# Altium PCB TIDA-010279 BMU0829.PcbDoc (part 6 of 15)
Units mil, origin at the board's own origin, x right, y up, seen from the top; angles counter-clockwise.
Board outline 11269.69 x 4438.98 mil, 4 copper layers (Top Layer, Signal Layer 1, Signal Layer 2, Bottom Layer), stack 61.6 mil thick; 1494 components, 725 nets, 3766 pads, 2728 vias.
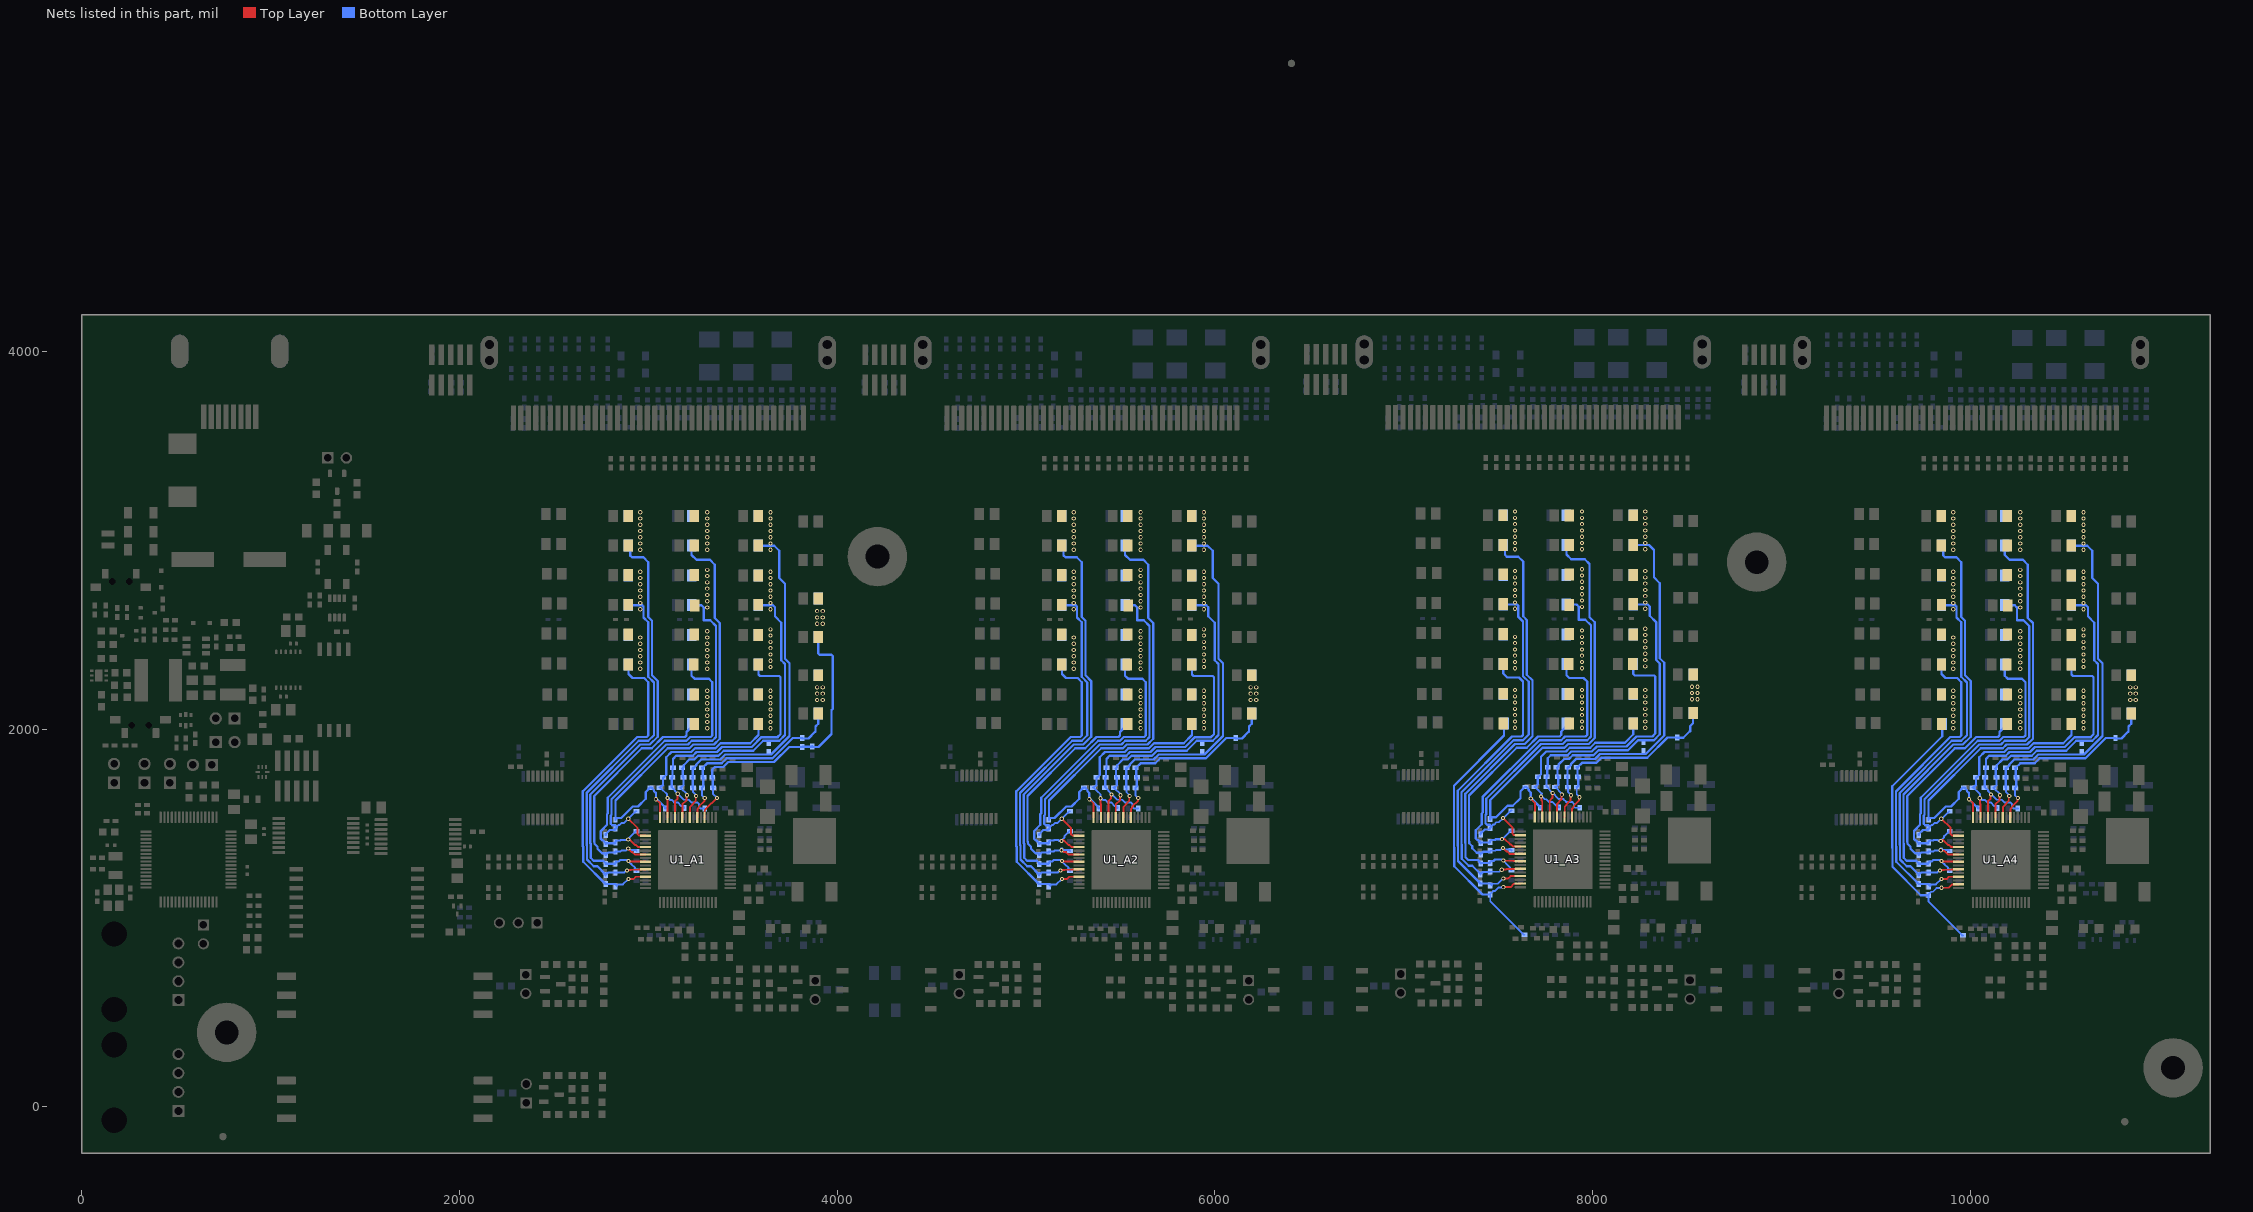
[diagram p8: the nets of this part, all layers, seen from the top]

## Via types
v1: diameter 22.01, hole 12.01, Top Layer to Bottom Layer, tented both sides, 2578 vias
v2: diameter 19.68, hole 7.87, Top Layer to Bottom Layer, tented both sides, 144 vias
v3: diameter 92.52, hole 49.21, Top Layer to Bottom Layer, 4 vias
v4: diameter 19.68, hole 7.87, Top Layer to Bottom Layer, 2 vias

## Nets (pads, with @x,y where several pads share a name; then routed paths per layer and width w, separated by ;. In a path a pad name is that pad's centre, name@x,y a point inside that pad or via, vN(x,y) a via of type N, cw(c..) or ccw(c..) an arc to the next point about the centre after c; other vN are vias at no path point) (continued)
CB4_A3: C15_A3.2 C34_A3.1 R27_A3.2 R30_A3.2 R33_A3.2 R38_A3.2 U1_A3.31 | length 1589.5
  Top Layer w10: v1@7525.45,1163.14 7564.79,1163.14 7582.95,1181.31 7615.77,1181.31 U1_A3.31@7616.67,1182.21
  Bottom Layer w10: C15_A3.2@7455.76,1125.64 7472.42,1142.3 7481.35,1142.3 7499.9,1160.85 7523.15,1160.85 v1@7525.45,1163.14 ; C15_A3.2@7457.73,1123.67 7457.73,1088.81 7635.64,910.9 C34_A3.1@7639.58,910.9
  Bottom Layer w12: C15_A3.2@7453.4,1123.67 7417.01,1123.67 7266.78,1273.91 7266.78,1371.84 7265.1,1373.52 7265.1,1700.42 7530.51,1965.84 R38_A3.2@7530.51,2029.14
  other v1: 7526.85,1163.14 7588.88,2007.46 7588.88,2040.64 7588.88,2073.83 7588.88,2107.01 7588.88,2140.2 7588.88,2173.38 7588.88,2206.57
CB4_A4: C15_A4.2 C34_A4.1 R27_A4.2 R30_A4.2 R33_A4.2 R38_A4.2 U1_A4.31 | length 1589.5
  Top Layer w10: v1@9845.68,1159.94 9885.02,1159.94 9903.18,1178.1 9936,1178.1 U1_A4.31@9936.9,1179
  Bottom Layer w10: C15_A4.2@9775.99,1122.43 9792.65,1139.09 9801.58,1139.09 9820.13,1157.64 9843.38,1157.64 v1@9845.68,1159.94 ; C15_A4.2@9777.96,1120.47 9777.96,1085.6 9955.87,907.69 C34_A4.1@9959.81,907.69
  Bottom Layer w12: C15_A4.2@9773.63,1120.47 9737.24,1120.47 9587.01,1270.7 9587.01,1368.63 9585.33,1370.32 9585.33,1697.21 9850.74,1962.63 R38_A4.2@9850.74,2025.93
  other v1: 9847.08,1159.94 9909.11,2004.25 9909.11,2037.44 9909.11,2070.62 9909.11,2103.81 9909.11,2136.99 9909.11,2170.17 9909.11,2203.36
CB5_A1: C2_A1.2 C15_A1.1 R13_A1.2 R16_A1.2 R20_A1.2 R23_A1.2 U1_A1.29 | length 1700.8
  Top Layer w10: v1@2893.84,1206.14 2921.43,1206.14 2933.66,1218.37 U1_A1.29@2985.06,1218.37
  Bottom Layer w10: C15_A1.1@2830.51,1175.39 2832.93,1177.81 2865.5,1177.81 v1@2893.84,1206.14
  Bottom Layer w12: C2_A1.2@2773.73,1179.32 2826.59,1179.32 2830.51,1175.39 2832.16,1173.75 C15_A1.1@2834.65,1171.26 ; C2_A1.2@2773.76,1179.35 2655.04,1298.07 2655.04,1376.87 2653.36,1378.55 2653.36,1670.23 2940.87,1957.75 2991.43,1957.75 2999.56,1965.88 2999.56,2248.51 2978.05,2270.02 2916.27,2270.02 2894.76,2291.52 R20_A1.2@2894.76,2341.02
  other v1: 2895.24,1206.14 2957.26,2319.21 2957.26,2352.4 2957.26,2385.58 2957.26,2418.77 2957.26,2451.95 2957.26,2485.14
CB5_A2: C2_A2.2 C15_A2.1 R13_A2.2 R16_A2.2 R20_A2.2 R23_A2.2 U1_A2.29 | length 1700.8
  Top Layer w10: v1@5188.85,1206.14 5216.44,1206.14 5228.67,1218.37 U1_A2.29@5280.07,1218.37
  Bottom Layer w10: C15_A2.1@5125.53,1175.39 5127.95,1177.81 5160.52,1177.81 v1@5188.85,1206.14
  Bottom Layer w12: C2_A2.2@5068.74,1179.32 5121.6,1179.32 5125.53,1175.39 5127.17,1173.75 C15_A2.1@5129.66,1171.26 ; C2_A2.2@5068.77,1179.35 4950.06,1298.07 4950.06,1376.87 4948.37,1378.55 4948.37,1670.23 5235.89,1957.75 5286.45,1957.75 5294.57,1965.88 5294.57,2248.51 5273.07,2270.02 5211.28,2270.02 5189.78,2291.52 R20_A2.2@5189.78,2341.02
  other v1: 5190.25,1206.14 5252.28,2319.21 5252.28,2352.4 5252.28,2385.58 5252.28,2418.77 5252.28,2451.95 5252.28,2485.14
CB5_A3: C2_A3.2 C15_A3.1 R13_A3.2 R16_A3.2 R20_A3.2 R23_A3.2 U1_A3.29 | length 1700.8
  Top Layer w10: v1@7525.45,1209.35 7553.04,1209.35 7565.27,1221.58 U1_A3.29@7616.67,1221.58
  Bottom Layer w10: C15_A3.1@7462.13,1178.6 7464.54,1181.02 7497.12,1181.02 v1@7525.45,1209.35
  Bottom Layer w12: C15_A3.1@7466.26,1174.47 7463.77,1176.96 7462.13,1178.6 7458.2,1182.53 C2_A3.2@7405.34,1182.53 7286.65,1301.28 7286.65,1380.07 7284.97,1381.76 7284.97,1673.44 7572.49,1960.96 7623.04,1960.96 7631.17,1969.08 7631.17,2251.72 7609.66,2273.22 7547.88,2273.22 7526.37,2294.73 R20_A3.2@7526.37,2344.23
  other v1: 7526.85,1209.35 7588.88,2322.42 7588.88,2355.6 7588.88,2388.79 7588.88,2421.97 7588.88,2455.16 7588.88,2488.34
CB5_A4: C2_A4.2 C15_A4.1 R13_A4.2 R16_A4.2 R20_A4.2 R23_A4.2 U1_A4.29 | length 1700.8
  Top Layer w10: v1@9845.68,1206.14 9873.27,1206.14 9885.5,1218.37 U1_A4.29@9936.9,1218.37
  Bottom Layer w10: C15_A4.1@9782.36,1175.39 9784.77,1177.81 9817.34,1177.81 v1@9845.68,1206.14
  Bottom Layer w12: C2_A4.2@9725.57,1179.32 9778.43,1179.32 9782.36,1175.39 9784,1173.75 C15_A4.1@9786.49,1171.26 ; C2_A4.2@9725.6,1179.35 9606.88,1298.07 9606.88,1376.87 9605.2,1378.55 9605.2,1670.23 9892.72,1957.75 9943.27,1957.75 9951.4,1965.88 9951.4,2248.51 9929.89,2270.02 9868.11,2270.02 9846.6,2291.52 R20_A4.2@9846.6,2341.02
  other v1: 9847.08,1206.14 9909.11,2319.21 9909.11,2352.4 9909.11,2385.58 9909.11,2418.77 9909.11,2451.95 9909.11,2485.14
CB6_A1: C2_A1.1 C94_A1.2 R1_A1.2 R4_A1.2 R7_A1.2 R10_A1.2 U1_A1.27 | length 1978.8
  Top Layer w10: v1(2886.57,1251.9) 2888.86,1254.2 2909.5,1254.2 2910.64,1255.34 2949.84,1255.34 2951.34,1256.84 2984.15,1256.84 U1_A1.27@2985.06,1257.74
  Bottom Layer w10: C94_A1.2@2826.12,1241.66 2873.08,1241.66 2883.32,1251.9 v1(2886.57,1251.9)
  Bottom Layer w12: C2_A1.1@2773.73,1226.56 C2_A1.1@2773.73,1230.5 ; C94_A1.2@2824.8,1240.16 2787.32,1240.16 2783.47,1236.31 2779.54,1236.31 C2_A1.1@2773.73,1230.5 ; R7_A1.2@2894.76,2656.12 2967.73,2656.12 2974.76,2649.09 2974.76,2590.68 2999.56,2565.88 2999.56,2276.61 3029.38,2246.79 3029.38,1967.59 2999.66,1937.87 2949.11,1937.87 2673.23,1662 2673.23,1386.78 2674.91,1385.1 2674.91,1310.04 2711.36,1273.59 2730.63,1273.59 C2_A1.1@2773.73,1230.5
  other v1: 2957.26,2634.17 2957.26,2667.36 2957.26,2700.54 2957.26,2733.73 2957.26,2766.91 2957.26,2800.1 2957.26,2833.28
CB6_A2: C2_A2.1 C94_A2.2 R1_A2.2 R4_A2.2 R7_A2.2 R10_A2.2 U1_A2.27 | length 1978.8
  Top Layer w10: v1(5181.58,1251.9) 5183.88,1254.2 5204.52,1254.2 5205.66,1255.34 5244.86,1255.34 5246.36,1256.84 5279.17,1256.84 U1_A2.27@5280.07,1257.74
  Bottom Layer w10: C94_A2.2@5121.14,1241.66 5168.1,1241.66 5178.33,1251.9 v1(5181.58,1251.9)
  Bottom Layer w12: C2_A2.1@5068.74,1226.56 C2_A2.1@5068.74,1230.5 ; C94_A2.2@5119.82,1240.16 5082.34,1240.16 5078.49,1236.31 5074.55,1236.31 C2_A2.1@5068.74,1230.5 ; R7_A2.2@5189.78,2656.12 5262.74,2656.12 5269.77,2649.09 5269.77,2590.68 5294.57,2565.88 5294.57,2276.61 5324.4,2246.79 5324.4,1967.59 5294.68,1937.87 5244.12,1937.87 4968.25,1662 4968.25,1386.78 4969.93,1385.1 4969.93,1310.04 5006.38,1273.59 5025.65,1273.59 C2_A2.1@5068.74,1230.5
  other v1: 5252.28,2634.17 5252.28,2667.36 5252.28,2700.54 5252.28,2733.73 5252.28,2766.91 5252.28,2800.1 5252.28,2833.28
CB6_A3: C2_A3.1 C94_A3.2 R1_A3.2 R4_A3.2 R7_A3.2 R10_A3.2 U1_A3.27 | length 1978.8
  Top Layer w10: v1(7518.18,1255.11) 7520.48,1257.41 7541.12,1257.41 7542.26,1258.55 7581.45,1258.55 7582.95,1260.05 7615.77,1260.05 U1_A3.27@7616.67,1260.95
  Bottom Layer w10: C94_A3.2@7457.73,1244.87 7504.69,1244.87 7514.93,1255.11 v1(7518.18,1255.11)
  Bottom Layer w12: C2_A3.1@7405.34,1229.77 C2_A3.1@7405.34,1233.71 ; C94_A3.2@7456.42,1243.37 7418.93,1243.37 7415.09,1239.52 7411.15,1239.52 C2_A3.1@7405.34,1233.71 ; R7_A3.2@7526.37,2659.32 7599.34,2659.32 7606.37,2652.29 7606.37,2593.89 7631.17,2569.09 7631.17,2279.82 7661,2250 7661,1970.8 7631.27,1941.08 7580.72,1941.08 7304.84,1665.21 7304.84,1389.99 7306.53,1388.31 7306.53,1313.25 7342.97,1276.8 7362.25,1276.8 C2_A3.1@7405.34,1233.71
  other v1: 7588.88,2637.38 7588.88,2670.57 7588.88,2703.75 7588.88,2736.93 7588.88,2770.12 7588.88,2803.3 7588.88,2836.49
CB6_A4: C2_A4.1 C94_A4.2 R1_A4.2 R4_A4.2 R7_A4.2 R10_A4.2 U1_A4.27 | length 1978.8
  Top Layer w10: v1(9838.41,1251.9) 9840.71,1254.2 9861.35,1254.2 9862.49,1255.34 9901.68,1255.34 9903.18,1256.84 9936,1256.84 U1_A4.27@9936.9,1257.74
  Bottom Layer w10: C94_A4.2@9777.96,1241.66 9824.92,1241.66 9835.16,1251.9 v1(9838.41,1251.9)
  Bottom Layer w12: C2_A4.1@9725.57,1226.56 C2_A4.1@9725.57,1230.5 ; C94_A4.2@9776.65,1240.16 9739.16,1240.16 9735.32,1236.31 9731.38,1236.31 C2_A4.1@9725.57,1230.5 ; R7_A4.2@9846.6,2656.12 9919.57,2656.12 9926.6,2649.09 9926.6,2590.68 9951.4,2565.88 9951.4,2276.62 9981.23,2246.79 9981.23,1967.59 9951.5,1937.87 9900.95,1937.87 9625.07,1662 9625.07,1386.78 9626.76,1385.1 9626.76,1310.04 9663.2,1273.59 9682.48,1273.59 C2_A4.1@9725.57,1230.5
  other v1: 9909.11,2634.17 9909.11,2667.36 9909.11,2700.54 9909.11,2733.73 9909.11,2766.91 9909.11,2800.1 9909.11,2833.28
CB7_A1: C73_A1.2 C94_A1.1 C97_A1.2 R70_A1.2 R73_A1.2 R77_A1.2 R81_A1.2 U1_A1.25 | length 2316.9
  Top Layer w10: v1@2895.24,1299.92 2949.43,1299.92 2951.34,1298.02 2984.15,1298.02 U1_A1.25@2985.06,1297.11
  Bottom Layer w10: v1@2893.96,1301.09 2909.85,1285.21 2909.85,1284.83 2929.76,1264.93 2929.76,1256.19 2936.57,1249.38 C97_A1.2@2938.47,1249.38
  Bottom Layer w12: C94_A1.1@2824.8,1289.37 2822.69,1287.25 2776.07,1287.25 C73_A1.2@2774.41,1285.6 2774.41,1289.54 2760.85,1303.1 2709.96,1303.1 2694.79,1318.27 2694.79,1393.33 2693.11,1395.01 2693.11,1653.77 2957.34,1918 3007.89,1918 3049.26,1959.36 3049.26,2255.02 3019.43,2284.85 3019.43,2574.11 2999.93,2593.61 2999.93,2883.66 2973.84,2909.75 2913.49,2909.75 2903.54,2919.7 2903.54,2962.42 R77_A1.2@2894.76,2971.21 ; C94_A1.1@2826.12,1292.84 2831.93,1298.65 2843.5,1298.65 2851.41,1306.56 2887.06,1306.56 2892.53,1301.09 2893.96,1301.09 v1(2895.24,1301.09)
  other v1: 2957.26,2949.13 2957.26,2982.32 2957.26,3015.5 2957.26,3048.69 2957.26,3081.87 2957.26,3115.06 2957.26,3148.24
CB7_A2: C73_A2.2 C94_A2.1 C97_A2.2 R70_A2.2 R73_A2.2 R77_A2.2 R81_A2.2 U1_A2.25 | length 2316.9
  Top Layer w10: v1@5190.25,1299.92 5244.45,1299.92 5246.36,1298.02 5279.17,1298.02 U1_A2.25@5280.07,1297.11
  Bottom Layer w10: v1@5188.98,1301.09 5204.87,1285.21 5204.87,1284.83 5224.77,1264.93 5224.77,1256.19 5231.58,1249.38 C97_A2.2@5233.49,1249.38
  Bottom Layer w12: C94_A2.1@5119.82,1289.37 5117.7,1287.25 5071.08,1287.25 C73_A2.2@5069.43,1285.6 5069.43,1289.54 5055.87,1303.1 5004.98,1303.1 4989.8,1318.27 4989.8,1393.33 4988.12,1395.01 4988.12,1653.77 5252.35,1918 5302.91,1918 5344.27,1959.36 5344.27,2255.02 5314.45,2284.85 5314.45,2574.11 5294.94,2593.61 5294.94,2883.66 5268.86,2909.75 5208.51,2909.75 5198.56,2919.7 5198.56,2962.42 R77_A2.2@5189.78,2971.21 ; C94_A2.1@5121.14,1292.84 5126.95,1298.65 5138.52,1298.65 5146.43,1306.56 5182.08,1306.56 5187.55,1301.09 5188.98,1301.09 v1(5190.25,1301.09)
  other v1: 5252.28,2949.13 5252.28,2982.32 5252.28,3015.5 5252.28,3048.69 5252.28,3081.87 5252.28,3115.06 5252.28,3148.24
CB7_A3: C73_A3.2 C94_A3.1 C97_A3.2 R70_A3.2 R73_A3.2 R77_A3.2 R81_A3.2 U1_A3.25 | length 2316.9
  Top Layer w10: v1@7526.85,1303.13 7581.05,1303.13 7582.95,1301.23 7615.77,1301.23 U1_A3.25@7616.67,1300.32
  Bottom Layer w10: v1@7525.58,1304.3 7541.47,1288.41 7541.47,1288.04 7561.37,1268.14 7561.37,1259.4 7568.18,1252.59 C97_A3.2@7570.09,1252.59
  Bottom Layer w12: C94_A3.1@7456.42,1292.58 7454.3,1290.46 7407.68,1290.46 C73_A3.2@7406.02,1288.81 7406.02,1292.75 7392.46,1306.31 7341.57,1306.31 7326.4,1321.48 7326.4,1396.54 7324.72,1398.22 7324.72,1656.97 7588.95,1921.21 7639.51,1921.21 7680.87,1962.57 7680.87,2258.23 7651.04,2288.06 7651.04,2577.32 7631.54,2596.82 7631.54,2886.87 7605.45,2912.96 7545.1,2912.96 7535.16,2922.9 7535.16,2965.63 R77_A3.2@7526.37,2974.42 ; C94_A3.1@7457.73,1296.05 7463.54,1301.86 7475.12,1301.86 7483.02,1309.77 7518.67,1309.77 7524.14,1304.3 7525.58,1304.3 v1(7526.85,1304.3)
  other v1: 7588.88,2952.34 7588.88,2985.53 7588.88,3018.71 7588.88,3051.9 7588.88,3085.08 7588.88,3118.27 7588.88,3151.45
CB7_A4: C73_A4.2 C94_A4.1 C97_A4.2 R70_A4.2 R73_A4.2 R77_A4.2 R81_A4.2 U1_A4.25 | length 2316.9
  Top Layer w10: v1@9847.08,1299.92 9901.28,1299.92 9903.18,1298.02 9936,1298.02 U1_A4.25@9936.9,1297.11
  Bottom Layer w10: v1@9845.81,1301.09 9861.69,1285.21 9861.69,1284.83 9881.6,1264.93 9881.6,1256.19 9888.41,1249.38 C97_A4.2@9890.32,1249.38
  Bottom Layer w12: C94_A4.1@9776.65,1289.37 9774.53,1287.25 9727.91,1287.25 C73_A4.2@9726.25,1285.6 9726.25,1289.54 9712.69,1303.1 9661.8,1303.1 9646.63,1318.28 9646.63,1393.33 9644.95,1395.01 9644.95,1653.77 9909.18,1918 9959.74,1918 10001.1,1959.36 10001.1,2255.02 9971.27,2284.85 9971.27,2574.11 9951.77,2593.61 9951.77,2883.66 9925.68,2909.75 9865.33,2909.75 9855.39,2919.7 9855.39,2962.42 R77_A4.2@9846.6,2971.21 ; C94_A4.1@9777.96,1292.84 9783.77,1298.65 9795.35,1298.65 9803.25,1306.56 9838.9,1306.56 9844.37,1301.09 9845.81,1301.09 v1(9847.08,1301.09)
  other v1: 9909.11,2949.13 9909.11,2982.32 9909.11,3015.5 9909.11,3048.69 9909.11,3081.87 9909.11,3115.06 9909.11,3148.24
CB8_A1: C53_A1.2 C73_A1.1 C90_A1.2 R56_A1.2 R59_A1.2 R63_A1.2 R67_A1.2 U1_A1.23 | length 1322.4
  Top Layer w10: v1(2893.54,1367.22) 2911.59,1349.17 2915.94,1349.17 2928.63,1336.48 U1_A1.23@2985.06,1336.48
  Bottom Layer w10: C53_A1.2@2826.12,1352.68 2852.08,1352.68 2856.32,1356.91 2880.07,1356.91 2890.37,1367.22 v1(2893.54,1367.22) 2896.79,1367.22 2903.74,1360.27 2932.78,1360.27 C90_A1.2@2938.47,1354.57
  Bottom Layer w12: C73_A1.1@2774.41,1332.84 C73_A1.1@2774.41,1336.78 ; C53_A1.2@2824.8,1348.43 2823.18,1346.81 2788.37,1346.81 2784.16,1342.59 2780.22,1342.59 C73_A1.1@2774.41,1336.78 ; R63_A1.2@3229.11,2025.93 3229.11,2011.43 3202.24,1984.56 3202.24,1966.23 3193.75,1957.75 3078.27,1957.75 3018.65,1898.13 2965.57,1898.13 2712.98,1645.53 2712.98,1403.24 2714.66,1401.56 2714.66,1392.6 2730.57,1376.69 2730.57,1366.52 2754.49,1342.59 2768.6,1342.59 C73_A1.1@2774.41,1336.78
  other v1: 3311.59,2004.25 3311.59,2037.44 3311.59,2070.62 3311.59,2103.81 3311.59,2136.99 3311.59,2170.17 3311.59,2203.36
CB8_A2: C53_A2.2 C73_A2.1 C90_A2.2 R56_A2.2 R59_A2.2 R63_A2.2 R67_A2.2 U1_A2.23 | length 1328.9
  Top Layer w10: v1(5187,1358.26) 5190.25,1358.26 5199.34,1349.17 5206.61,1349.17 5210.96,1349.17 5223.64,1336.48 U1_A2.23@5280.07,1336.48
  Bottom Layer w10: C53_A2.2@5121.14,1352.68 5147.1,1352.68 5151.34,1356.91 5175.08,1356.91 5185.39,1367.22 5191.81,1367.22 5198.76,1360.27 5227.79,1360.27 C90_A2.2@5233.49,1354.57 ; v1@5183.79,1365.62 5187,1362.41 v1(5187,1358.26)
  Bottom Layer w12: C73_A2.1@5069.43,1332.84 C73_A2.1@5069.43,1336.78 ; C53_A2.2@5119.82,1348.43 5118.2,1346.81 5083.39,1346.81 5079.18,1342.59 5075.24,1342.59 C73_A2.1@5069.43,1336.78 ; R63_A2.2@5524.12,2025.93 5524.12,2011.43 5497.25,1984.56 5497.25,1966.23 5488.77,1957.75 5373.29,1957.75 5313.67,1898.13 5260.59,1898.13 5007.99,1645.53 5007.99,1403.24 5009.68,1401.56 5009.68,1392.6 5025.58,1376.69 5025.58,1366.52 5049.51,1342.59 5063.62,1342.59 C73_A2.1@5069.43,1336.78
  other v1: 5606.61,2004.25 5606.61,2037.44 5606.61,2070.62 5606.61,2103.81 5606.61,2136.99 5606.61,2170.17 5606.61,2203.36
CB8_A3: C53_A3.2 C73_A3.1 C90_A3.2 R56_A3.2 R59_A3.2 R63_A3.2 R67_A3.2 U1_A3.23 | length 1322.4
  Top Layer w10: v1(7525.15,1370.43) 7543.2,1352.38 7547.55,1352.38 7560.24,1339.69 U1_A3.23@7616.67,1339.69
  Bottom Layer w10: C53_A3.2@7457.73,1355.89 7483.7,1355.89 7487.93,1360.12 7511.68,1360.12 7521.98,1370.43 v1(7525.15,1370.43) 7528.4,1370.43 7535.35,1363.48 7564.39,1363.48 C90_A3.2@7570.09,1357.78
  Bottom Layer w12: C73_A3.1@7406.02,1336.05 C73_A3.1@7406.02,1339.99 ; C53_A3.2@7456.42,1351.63 7454.8,1350.01 7419.99,1350.01 7415.77,1345.8 7411.84,1345.8 C73_A3.1@7406.02,1339.99 ; R63_A3.2@7860.72,2029.14 7860.72,2014.63 7833.85,1987.76 7833.85,1969.44 7825.36,1960.96 7709.89,1960.96 7650.27,1901.33 7597.18,1901.33 7344.59,1648.74 7344.59,1406.45 7346.27,1404.77 7346.27,1395.8 7362.18,1379.9 7362.18,1369.73 7386.1,1345.8 7400.21,1345.8 C73_A3.1@7406.02,1339.99
  other v1: 7943.21,2007.46 7943.21,2040.64 7943.21,2073.83 7943.21,2107.01 7943.21,2140.2 7943.21,2173.38 7943.21,2206.57
CB8_A4: C53_A4.2 C73_A4.1 C90_A4.2 R56_A4.2 R59_A4.2 R63_A4.2 R67_A4.2 U1_A4.23 | length 1328.9
  Top Layer w10: v1(9842.5,1358.26) 9844.8,1355.97 9860.98,1355.97 9880.47,1336.48 U1_A4.23@9936.9,1336.48
  Bottom Layer w10: C53_A4.2@9777.96,1352.68 9803.93,1352.68 9808.16,1356.91 9831.91,1356.91 9842.21,1367.22 9848.63,1367.22 9855.58,1360.27 9884.62,1360.27 C90_A4.2@9890.32,1354.57 ; v1@9839.29,1364.3 9842.5,1361.09 v1(9842.5,1358.26)
  Bottom Layer w12: C73_A4.1@9726.25,1332.84 C73_A4.1@9726.25,1336.78 ; C53_A4.2@9776.65,1348.43 9775.03,1346.81 9740.22,1346.81 9736,1342.59 9732.07,1342.59 C73_A4.1@9726.25,1336.78 ; R63_A4.2@10180.95,2025.93 10180.95,2011.43 10154.08,1984.56 10154.08,1966.23 10145.59,1957.75 10030.12,1957.75 9970.5,1898.13 9917.41,1898.13 9664.82,1645.53 9664.82,1403.24 9666.5,1401.56 9666.5,1392.6 9682.41,1376.69 9682.41,1366.52 9706.33,1342.59 9720.44,1342.59 C73_A4.1@9726.25,1336.78
  other v1: 10263.44,2004.25 10263.44,2037.44 10263.44,2070.62 10263.44,2103.81 10263.44,2136.99 10263.44,2170.17 10263.44,2203.36
CB9_A1: C35_A1.2 C53_A1.1 C85_A1.2 R43_A1.2 R46_A1.2 R49_A1.2 R53_A1.2 U1_A1.21 | length 1721.7
  Top Layer w10: v1(2893.51,1414.98) 2894.12,1414.37 2902.61,1414.37 2930.79,1386.19 2934.77,1386.19 2945.11,1375.85 U1_A1.21@2985.06,1375.85
  Bottom Layer w10: v1(2893.51,1414.98) 2895.8,1417.28 2895.8,1421.03 2934.54,1459.77 C85_A1.2@2938.47,1459.77
  Bottom Layer w12: C35_A1.2@2774.41,1392.3 2778.22,1396.11 2823.28,1396.11 C53_A1.1@2824.8,1397.64 ; C35_A1.2@2774.41,1396.24 2760.73,1409.92 2756.85,1409.92 2748.73,1418.05 2748.73,1461.04 2780.56,1492.88 2780.56,1549.77 2785.43,1554.64 2785.43,1636.8 3086.51,1937.87 3201.98,1937.87 3221.86,1957.75 3330.74,1957.75 3338.86,1965.88 3338.86,2248.51 3320.18,2267.19 3243.96,2267.19 3229.11,2282.04 R49_A1.2@3229.11,2341.02 ; C53_A1.1@2826.12,1403.86 2831.93,1409.67 2850.48,1409.67 2854.09,1413.29 2891.81,1413.29 v1(2893.51,1414.98)
  other v1: 3311.59,2319.21 3311.59,2352.4 3311.59,2385.58 3311.59,2418.77 3311.59,2451.95 3311.59,2485.14 3311.59,2518.32
CB9_A2: C35_A2.2 C53_A2.1 C85_A2.2 R43_A2.2 R46_A2.2 R49_A2.2 R53_A2.2 U1_A2.21 | length 1734.5
  Top Layer w10: v1(5187,1407.48) 5190.25,1407.48 5197.14,1414.37 5197.63,1414.37 5225.8,1386.19 5229.79,1386.19 5240.13,1375.85 U1_A2.21@5280.07,1375.85
  Bottom Layer w10: v1(5187,1407.48) 5187,1410.14 5204.05,1427.2 5204.05,1434.27 5229.55,1459.77 C85_A2.2@5233.49,1459.77
  Bottom Layer w12: C35_A2.2@5069.43,1392.3 5073.24,1396.11 5118.29,1396.11 C53_A2.1@5119.82,1397.64 ; C35_A2.2@5069.43,1396.24 5055.74,1409.92 5051.87,1409.92 5043.74,1418.05 5043.74,1461.04 5075.58,1492.88 5075.58,1549.77 5080.45,1554.64 5080.45,1636.8 5381.52,1937.87 5497,1937.87 5516.87,1957.75 5625.75,1957.75 5633.88,1965.88 5633.88,2248.51 5615.19,2267.19 5538.97,2267.19 5524.12,2282.04 R49_A2.2@5524.12,2341.02 ; C53_A2.1@5121.14,1403.86 5126.95,1409.67 5145.49,1409.67 5149.11,1413.29 5169.72,1413.29 5173.61,1409.39 5184.29,1409.39 v1@5187,1412.1
  other v1: 5606.61,2319.21 5606.61,2352.4 5606.61,2385.58 5606.61,2418.77 5606.61,2451.95 5606.61,2485.14 5606.61,2518.32
CB9_A3: C35_A3.2 C53_A3.1 C85_A3.2 R43_A3.2 R46_A3.2 R49_A3.2 R53_A3.2 U1_A3.21 | length 1727.8
  Top Layer w10: v1(7519.67,1417.32) 7519.93,1417.58 7534.22,1417.58 7562.4,1389.4 7566.38,1389.4 7576.72,1379.06 U1_A3.21@7616.67,1379.06
  Bottom Layer w10: v1(7519.67,1417.32) 7520.5,1417.32 7566.15,1462.97 C85_A3.2@7570.09,1462.97
  Bottom Layer w12: C35_A3.2@7406.02,1395.51 7409.83,1399.32 7454.89,1399.32 C53_A3.1@7456.42,1400.85 ; C35_A3.2@7406.02,1399.45 7392.34,1413.13 7388.47,1413.13 7380.34,1421.26 7380.34,1464.25 7412.17,1496.08 7412.17,1552.98 7417.05,1557.85 7417.05,1640.01 7718.12,1941.08 7833.6,1941.08 7853.47,1960.96 7962.35,1960.96 7970.48,1969.08 7970.48,2251.72 7951.79,2270.4 7875.57,2270.4 7860.72,2285.25 R49_A3.2@7860.72,2344.23 ; C53_A3.1@7457.73,1407.07 7463.54,1412.88 7482.09,1412.88 7485.7,1416.49 7521.77,1416.49 v1@7522.6,1417.32
  other v1: 7943.21,2322.42 7943.21,2355.6 7943.21,2388.79 7943.21,2421.97 7943.21,2455.16 7943.21,2488.34 7943.21,2521.53
CB9_A4: C35_A4.2 C53_A4.1 C85_A4.2 R43_A4.2 R46_A4.2 R49_A4.2 R53_A4.2 U1_A4.21 | length 1732.1
  Top Layer w10: v1(9842.5,1407.48) 9845.75,1407.48 9852.64,1414.37 9854.45,1414.37 9882.63,1386.19 9886.61,1386.19 9896.95,1375.85 U1_A4.21@9936.9,1375.85
  Bottom Layer w10: v1@9842.5,1412.13 9842.56,1412.07 9845.75,1412.07 9860.22,1426.53 9860.22,1433.61 9886.38,1459.77 C85_A4.2@9890.32,1459.77
  Bottom Layer w12: C35_A4.2@9726.25,1392.3 9730.06,1396.11 9775.12,1396.11 C53_A4.1@9776.65,1397.64 ; C35_A4.2@9726.25,1396.24 9712.57,1409.92 9708.7,1409.92 9700.57,1418.05 9700.57,1461.04 9732.4,1492.88 9732.4,1549.77 9737.28,1554.64 9737.28,1636.8 10038.35,1937.87 10153.83,1937.87 10173.7,1957.75 10282.58,1957.75 10290.71,1965.88 10290.71,2248.51 10272.02,2267.19 10195.8,2267.19 10180.95,2282.04 R49_A4.2@10180.95,2341.02 ; C53_A4.1@9777.96,1403.86 9783.77,1409.67 9802.32,1409.67 9805.93,1413.29 9826.54,1413.29 9830.44,1409.39 9840.59,1409.39 v1(9842.5,1407.48)
  other v1: 10263.44,2319.21 10263.44,2352.4 10263.44,2385.58 10263.44,2418.77 10263.44,2451.95 10263.44,2485.14 10263.44,2518.32
CB10_A1: C16_A1.2 C35_A1.1 C80_A1.2 R28_A1.2 R31_A1.2 R34_A1.2 R39_A1.2 U1_A1.18 | length 2026.9
  Top Layer w10: v1(2893.7,1525.59) 2942.66,1476.63 2942.66,1444.5 2951.34,1435.81 2984.15,1435.81 U1_A1.18@2985.06,1434.91
  Bottom Layer w10: C16_A1.2@2832.12,1482.74 2840.81,1491.42 2846.57,1491.42 2858.57,1503.42 2871.53,1503.42 v1(2893.7,1525.59) ; v1@2897.54,1527.96 2934.54,1564.96 C80_A1.2@2938.47,1564.96
  Bottom Layer w12: C35_A1.1@2774.41,1439.55 2774.41,1443.48 2796.31,1465.38 2820.31,1465.38 2824.8,1469.87 C16_A1.2@2824.8,1473.93 ; C16_A1.2@2827.25,1473.93 2832.12,1478.8 2832.12,1482.74 2824.44,1490.42 2808.56,1490.42 2800.44,1498.55 2800.44,1541.54 2805.31,1546.41 2805.31,1628.57 3094.74,1918 3210.22,1918 3230.09,1937.87 3338.97,1937.87 3358.74,1957.64 3358.74,2546 3328.43,2576.31 3293.92,2576.31 3293.92,2644.21 3282.02,2656.12 R39_A1.2@3229.11,2656.12
  other v1: 3311.59,2644.02 3311.59,2677.2 3311.59,2710.38 3311.59,2743.57 3311.59,2776.75 3311.59,2809.94 3311.59,2843.12
CB10_A2: C16_A2.2 C35_A2.1 C80_A2.2 R28_A2.2 R31_A2.2 R34_A2.2 R39_A2.2 U1_A2.18 | length 2026.9
  Top Layer w10: v1(5188.72,1525.59) 5237.67,1476.63 5237.67,1444.5 5246.36,1435.81 5279.17,1435.81 U1_A2.18@5280.07,1434.91
  Bottom Layer w10: C16_A2.2@5127.14,1482.74 5135.82,1491.42 5141.59,1491.42 5153.58,1503.42 5166.55,1503.42 v1(5188.72,1525.59) ; v1@5192.55,1527.96 5229.55,1564.96 C80_A2.2@5233.49,1564.96
  Bottom Layer w12: C35_A2.1@5069.43,1439.55 5069.43,1443.48 5091.33,1465.38 5115.33,1465.38 5119.82,1469.87 C16_A2.2@5119.82,1473.93 ; C16_A2.2@5122.27,1473.93 5127.14,1478.8 5127.14,1482.74 5119.45,1490.42 5103.58,1490.42 5095.45,1498.55 5095.45,1541.54 5100.32,1546.41 5100.32,1628.57 5389.75,1918 5505.23,1918 5525.11,1937.87 5633.98,1937.87 5653.75,1957.64 5653.75,2546 5623.45,2576.31 5588.94,2576.31 5588.94,2644.21 5577.04,2656.12 R39_A2.2@5524.12,2656.12
  other v1: 5606.61,2644.02 5606.61,2677.2 5606.61,2710.38 5606.61,2743.57 5606.61,2776.75 5606.61,2809.94 5606.61,2843.12
CB10_A3: C16_A3.2 C35_A3.1 C80_A3.2 R28_A3.2 R31_A3.2 R34_A3.2 R39_A3.2 U1_A3.18 | length 2026.9
  Top Layer w10: v1(7525.31,1528.8) 7574.27,1479.84 7574.27,1447.71 7582.95,1439.02 7615.77,1439.02 U1_A3.18@7616.67,1438.12
  Bottom Layer w10: C16_A3.2@7463.73,1485.95 7472.42,1494.63 7478.18,1494.63 7490.18,1506.63 7503.14,1506.63 v1(7525.31,1528.8) ; v1@7529.15,1531.17 7566.15,1568.17 C80_A3.2@7570.09,1568.17
  Bottom Layer w12: C35_A3.1@7406.02,1442.75 7406.02,1446.69 7427.92,1468.59 7451.92,1468.59 7456.42,1473.08 C16_A3.2@7456.42,1477.14 ; C16_A3.2@7458.86,1477.14 7463.73,1482.01 7463.73,1485.95 7456.05,1493.63 7440.18,1493.63 7432.05,1501.76 7432.05,1544.75 7436.92,1549.62 7436.92,1631.78 7726.35,1921.21 7841.83,1921.21 7861.7,1941.08 7970.58,1941.08 7990.35,1960.85 7990.35,2549.21 7960.04,2579.52 7925.54,2579.52 7925.54,2647.42 7913.63,2659.32 R39_A3.2@7860.72,2659.32
  other v1: 7943.21,2647.22 7943.21,2680.41 7943.21,2713.59 7943.21,2746.78 7943.21,2779.96 7943.21,2813.15 7943.21,2846.33
CB10_A4: C16_A4.2 C35_A4.1 C80_A4.2 R28_A4.2 R31_A4.2 R34_A4.2 R39_A4.2 U1_A4.18 | length 2026.9
  Top Layer w10: v1(9845.54,1525.59) 9894.5,1476.64 9894.5,1444.5 9903.18,1435.81 9936,1435.81 U1_A4.18@9936.9,1434.91
  Bottom Layer w10: C16_A4.2@9783.96,1482.74 9792.65,1491.42 9798.41,1491.42 9810.41,1503.42 9823.37,1503.42 v1(9845.54,1525.59) ; v1@9849.38,1527.96 9886.38,1564.96 C80_A4.2@9890.32,1564.96
  Bottom Layer w12: C35_A4.1@9726.25,1439.55 9726.25,1443.48 9748.15,1465.38 9772.15,1465.38 9776.65,1469.87 C16_A4.2@9776.65,1473.93 ; C16_A4.2@9779.09,1473.93 9783.96,1478.8 9783.96,1482.74 9776.28,1490.42 9760.41,1490.42 9752.28,1498.55 9752.28,1541.54 9757.15,1546.41 9757.15,1628.57 10046.58,1918 10162.06,1918 10181.93,1937.87 10290.81,1937.87 10310.58,1957.64 10310.58,2546 10280.27,2576.31 10245.77,2576.31 10245.77,2644.21 10233.86,2656.12 R39_A4.2@10180.95,2656.12
  other v1: 10263.44,2644.02 10263.44,2677.2 10263.44,2710.38 10263.44,2743.57 10263.44,2776.75 10263.44,2809.94 10263.44,2843.12
CB11_A1: C3_A1.2 C16_A1.1 C76_A1.2 R14_A1.2 R17_A1.2 R21_A1.2 R24_A1.2 U1_A1.16 | length 2439.1
  Top Layer w10: v1(3039.95,1628.88) 3061.83,1607 U1_A1.16@3061.83,1531.37
  Bottom Layer w12: C16_A1.1@2826.12,1520.04 2826.12,1523.79 2831.93,1529.6 2855.93,1529.6 2916.98,1590.65 2945.15,1590.65 2985.79,1631.28 2985.79,1667.36 3008.57,1690.14 C3_A1.2@3012.51,1690.14 3016.45,1690.14 3030.13,1676.46 3030.13,1671.2 3039.95,1661.38 v1(3039.95,1628.88) 3041.87,1626.97 3046.76,1626.97 3089.39,1584.33 C76_A1.2@3089.39,1580.39 ; C16_A1.1@2826.12,1529.6 2826.12,1621.28 3102.97,1898.13 3218.45,1898.13 3238.32,1918 3347.2,1918 3378.61,1949.41 3378.61,2561.89 3351.83,2588.66 3351.83,2870.28 3326.12,2895.99 3254.82,2895.99 3229.11,2921.71 R17_A1.2@3229.11,2971.21
  other v1: 3311.59,2949.13 3311.59,2982.32 3311.59,3015.5 3311.59,3048.69 3311.59,3081.87 3311.59,3115.06 3311.59,3148.24
CB11_A2: C3_A2.2 C16_A2.1 C76_A2.2 R14_A2.2 R17_A2.2 R21_A2.2 R24_A2.2 U1_A2.16 | length 2439.1
  Top Layer w10: v1(5334.97,1628.88) 5356.85,1607 U1_A2.16@5356.85,1531.37
  Bottom Layer w12: C16_A2.1@5121.14,1520.04 5121.14,1523.79 5126.95,1529.6 5150.95,1529.6 5212,1590.65 5240.17,1590.65 5280.81,1631.28 5280.81,1667.36 5303.59,1690.14 C3_A2.2@5307.52,1690.14 5311.46,1690.14 5325.15,1676.46 5325.15,1671.2 5334.97,1661.38 v1(5334.97,1628.88) 5336.88,1626.97 5341.77,1626.97 5384.41,1584.33 C76_A2.2@5384.41,1580.39 ; C16_A2.1@5121.14,1529.6 5121.14,1621.28 5397.99,1898.13 5513.46,1898.13 5533.34,1918 5642.22,1918 5673.63,1949.41 5673.63,2561.89 5646.85,2588.66 5646.85,2870.28 5621.13,2895.99 5549.84,2895.99 5524.12,2921.71 R17_A2.2@5524.12,2971.21
  other v1: 5606.61,2949.13 5606.61,2982.32 5606.61,3015.5 5606.61,3048.69 5606.61,3081.87 5606.61,3115.06 5606.61,3148.24
CB11_A3: C3_A3.2 C16_A3.1 C76_A3.2 R14_A3.2 R17_A3.2 R21_A3.2 R24_A3.2 U1_A3.16 | length 2439.1
  Top Layer w10: v1(7671.56,1632.09) 7693.44,1610.21 U1_A3.16@7693.44,1534.57
  Bottom Layer w12: C16_A3.1@7457.73,1523.25 7457.73,1526.99 7463.54,1532.81 7487.54,1532.81 7548.59,1593.85 7576.77,1593.85 7617.4,1634.49 7617.4,1670.57 7640.18,1693.35 C3_A3.2@7644.12,1693.35 7648.06,1693.35 7661.74,1679.67 7661.74,1674.41 7671.56,1664.59 v1(7671.56,1632.09) 7673.48,1630.18 7678.37,1630.18 7721.01,1587.54 C76_A3.2@7721.01,1583.6 ; C16_A3.1@7457.73,1532.81 7457.73,1624.48 7734.58,1901.33 7850.06,1901.33 7869.93,1921.21 7978.81,1921.21 8010.22,1952.62 8010.22,2565.09 7983.45,2591.87 7983.45,2873.48 7957.73,2899.2 7886.44,2899.2 7860.72,2924.92 R17_A3.2@7860.72,2974.42
  other v1: 7943.21,2952.34 7943.21,2985.53 7943.21,3018.71 7943.21,3051.9 7943.21,3085.08 7943.21,3118.27 7943.21,3151.45
CB11_A4: C3_A4.2 C16_A4.1 C76_A4.2 R14_A4.2 R17_A4.2 R21_A4.2 R24_A4.2 U1_A4.16 | length 2439.1
  Top Layer w10: v1(9991.79,1628.88) 10013.67,1607 U1_A4.16@10013.67,1531.37
  Bottom Layer w12: C16_A4.1@9777.96,1520.05 9777.96,1523.79 9783.77,1529.6 9807.77,1529.6 9868.82,1590.65 9897,1590.65 9937.63,1631.28 9937.63,1667.36 9960.41,1690.14 C3_A4.2@9964.35,1690.14 9968.29,1690.14 9981.97,1676.46 9981.97,1671.2 9991.79,1661.38 v1(9991.79,1628.88) 10030.53,1590.14 10035.42,1590.14 10041.24,1584.33 C76_A4.2@10041.24,1580.39 ; C16_A4.1@9777.96,1529.6 9777.96,1621.28 10054.81,1898.13 10170.29,1898.13 10190.16,1918 10299.04,1918 10330.45,1949.41 10330.45,2561.89 10303.68,2588.66 10303.68,2870.28 10277.96,2895.99 10206.67,2895.99 10180.95,2921.71 R17_A4.2@10180.95,2971.21
  other v1: 10263.44,2949.13 10263.44,2982.32 10263.44,3015.5 10263.44,3048.69 10263.44,3081.87 10263.44,3115.06 10263.44,3148.24
CB12_A1: C3_A1.1 C68_A1.2 C95_A1.2 R2_A1.2 R5_A1.2 R8_A1.2 R11_A1.2 U1_A1.14 | length 1061.5
  Top Layer w10: U1_A1.14@3101.2,1531.37 v1(3101.15,1635.58)
  Bottom Layer w10: C3_A1.1@3063.69,1690.14 3080.03,1673.81 3080.31,1673.81 3098.9,1655.21 3098.9,1637.83 v1(3101.15,1635.58) 3104.4,1635.58 3114.88,1625.09 3123.41,1625.09 3136.78,1611.72 3154.74,1611.72 3174.35,1592.12 3182.76,1592.12 3189.57,1585.31 C68_A1.2@3189.57,1581.37
  Bottom Layer w12: C3_A1.1@3059.75,1690.14 3063.69,1690.14 3077.49,1703.94 C95_A1.2@3077.49,1744.01 3081.42,1744.01 3095.11,1757.7 3095.11,1850.76 3122.6,1878.25 3226.68,1878.25 3246.55,1898.13 3355.43,1898.13 3382.18,1924.87 3539.05,1924.87 3583.08,1968.91 R5_A1.2@3583.08,2025.93
  other v1: 3646.24,2004.25 3646.24,2037.44 3646.24,2070.62 3646.24,2103.81 3646.24,2136.99 3646.24,2170.17 3646.24,2203.36
CB12_A2: C3_A2.1 C68_A2.2 C95_A2.2 R2_A2.2 R5_A2.2 R8_A2.2 R11_A2.2 U1_A2.14 | length 1059.4
  Top Layer w10: v1(5393.69,1633.86) 5393.69,1605.35 5396.19,1602.85 U1_A2.14@5396.22,1531.37
  Bottom Layer w10: C3_A2.1@5358.71,1690.14 5375.04,1673.81 5375.32,1673.81 5393.92,1655.21 v1@5393.92,1637.83 ; v1(5393.69,1633.86) 5396.94,1633.86 5405.7,1625.09 5418.42,1625.09 5431.79,1611.72 5449.76,1611.72 5469.36,1592.12 5477.77,1592.12 5484.59,1585.31 C68_A2.2@5484.59,1581.37
  Bottom Layer w12: C3_A2.1@5354.77,1690.14 5358.71,1690.14 5372.5,1703.94 C95_A2.2@5372.5,1744.01 5376.44,1744.01 5390.12,1757.7 5390.12,1850.76 5417.61,1878.25 5521.7,1878.25 5541.57,1898.13 5650.45,1898.13 5677.2,1924.87 5834.06,1924.87 5878.1,1968.91 R5_A2.2@5878.1,2025.93
  other v1: 5941.25,2004.25 5941.25,2037.44 5941.25,2070.62 5941.25,2103.81 5941.25,2136.99 5941.25,2170.17 5941.25,2203.36
CB12_A3: C3_A3.1 C68_A3.2 C95_A3.2 R2_A3.2 R5_A3.2 R8_A3.2 R11_A3.2 U1_A3.14 | length 1073.6
  Top Layer w10: v1(7726.36,1643.7) 7728.66,1641.4 7728.66,1622.72 7732.79,1618.59 U1_A3.14@7732.81,1534.57
  Bottom Layer w10: C3_A3.1@7695.3,1693.35 7711.64,1677.01 7711.92,1677.01 7730.51,1658.42 7728.66,1656.57 7728.66,1646 v1(7726.36,1643.7) ; v1@7726.36,1638.58 7729.19,1641.4 7731.91,1641.4 7745.01,1628.3 7755.02,1628.3 7768.39,1614.93 7786.35,1614.93 7805.96,1595.33 7814.37,1595.33 7821.18,1588.52 C68_A3.2@7821.18,1584.58
  Bottom Layer w12: C3_A3.1@7691.36,1693.35 7695.3,1693.35 7709.1,1707.15 C95_A3.2@7709.1,1747.22 7713.04,1747.22 7726.72,1760.91 7726.72,1853.97 7754.21,1881.46 7858.29,1881.46 7878.17,1901.33 7987.04,1901.33 8013.79,1928.08 8170.66,1928.08 8214.69,1972.12 R5_A3.2@8214.69,2029.14
  other v1: 8277.85,2007.46 8277.85,2040.64 8277.85,2073.83 8277.85,2107.01 8277.85,2140.2 8277.85,2173.38 8277.85,2206.57
CB12_A4: C3_A4.1 C68_A4.2 C95_A4.2 R2_A4.2 R5_A4.2 R8_A4.2 R11_A4.2 U1_A4.14 | length 1065.8
  Top Layer w10: v1(10049.19,1633.86) 10050.23,1632.82 10050.23,1605.64 10053.02,1602.85 U1_A4.14@10053.04,1531.37
  Bottom Layer w10: C3_A4.1@10015.53,1690.14 10031.87,1673.81 10032.15,1673.81 10050.74,1655.21 10050.74,1635.41 v1(10049.19,1633.86) 10052.44,1633.86 10061.2,1625.09 10075.25,1625.09 10088.62,1611.72 10106.58,1611.72 10126.19,1592.12 10134.6,1592.12 10141.41,1585.31 C68_A4.2@10141.41,1581.37
  Bottom Layer w12: C3_A4.1@10011.59,1690.14 10015.53,1690.14 10029.33,1703.94 C95_A4.2@10029.33,1744.01 10033.27,1744.01 10046.95,1757.7 10046.95,1850.76 10074.44,1878.25 10178.52,1878.25 10198.4,1898.13 10307.27,1898.13 10334.02,1924.87 10490.89,1924.87 10534.92,1968.91 R5_A4.2@10534.92,2025.93
  other v1: 10598.08,2004.25 10598.08,2037.44 10598.08,2070.62 10598.08,2103.81 10598.08,2136.99 10598.08,2170.17 10598.08,2203.36
CB13_A1: C62_A1.2 C74_A1.2 C95_A1.1 R71_A1.2 R74_A1.2 R78_A1.2 R82_A1.2 R196_A1.2 U1_A1.12 | length 1617.1
  Top Layer w10: U1_A1.12@3140.57,1531.37 3140.57,1617.78 3154.85,1632.06 3154.85,1657.33 v1(3155.59,1658.07)
  Bottom Layer w10: C74_A1.2@3126.42,1690.24 3141.11,1675.56 3141.11,1672.88 3155.59,1658.4 v1(3155.59,1658.07) ; v1@3152.84,1661.15 3153.04,1661.15 3188.33,1625.87 3213.29,1625.87 3227.43,1611.72 3258.72,1611.72 3268.97,1601.47 3268.97,1586.37 3274.83,1580.51 3298.84,1580.51 C62_A1.2@3298.96,1580.39
  Bottom Layer w12: C74_A1.2@3123.61,1693.06 3123.61,1742.89 C95_A1.1@3124.73,1744.01 3127.53,1746.82 3127.53,1793.1 R196_A1.2@3130.34,1795.9 3130.34,1842.08 3146.63,1858.38 3234.91,1858.38 3254.79,1878.25 3363.66,1878.25 3390.41,1905 3547.28,1905 3599.78,1957.5 3684.47,1957.5 3699.82,1972.85 3699.82,2273.94 3692.79,2280.97 3591.1,2280.97 3583.08,2288.99 R71_A1.2@3583.08,2341.02
  other v1: 3646.24,2329.05 3646.24,2362.24 3646.24,2395.42 3646.24,2428.61 3646.24,2461.79 3646.24,2494.98 3646.24,2528.16
CB13_A2: C62_A2.2 C74_A2.2 C95_A2.1 R71_A2.2 R74_A2.2 R78_A2.2 R82_A2.2 R196_A2.2 U1_A2.12 | length 1610
  Top Layer w10: U1_A2.12@5435.59,1531.37 5435.59,1617.78 5450.45,1632.65 5450.45,1651.24 v1(5452.74,1653.54)
  Bottom Layer w10: C74_A2.2@5421.44,1690.24 5436.12,1675.56 5436.12,1672.88 5452.74,1656.26 v1(5452.74,1653.54) ; v1@5454.21,1655 5483.34,1625.87 5508.3,1625.87 5522.45,1611.72 5553.74,1611.72 5563.99,1601.47 5563.99,1586.37 5569.84,1580.51 5593.85,1580.51 C62_A2.2@5593.97,1580.39
  Bottom Layer w12: C74_A2.2@5418.62,1693.06 5418.62,1742.89 C95_A2.1@5419.75,1744.01 5422.55,1746.82 5422.55,1793.1 R196_A2.2@5425.35,1795.9 5425.35,1842.08 5441.65,1858.38 5529.93,1858.38 5549.8,1878.25 5658.68,1878.25 5685.43,1905 5842.3,1905 5894.8,1957.5 5979.48,1957.5 5994.83,1972.85 5994.83,2273.94 5987.8,2280.97 5886.11,2280.97 5878.1,2288.99 R71_A2.2@5878.1,2341.02
  other v1: 5941.25,2329.05 5941.25,2362.24 5941.25,2395.42 5941.25,2428.61 5941.25,2461.79 5941.25,2494.98 5941.25,2528.16
CB13_A3: C62_A3.2 C74_A3.2 C95_A3.1 R71_A3.2 R74_A3.2 R78_A3.2 R82_A3.2 R196_A3.2 U1_A3.12 | length 1617.8
  Top Layer w10: U1_A3.12@7772.18,1534.57 7772.18,1620.99 7786.46,1635.27 7786.46,1659.8 v1(7787.94,1661.28)
  Bottom Layer w10: C74_A3.2@7758.04,1693.45 7772.72,1678.76 7772.72,1676.09 7787.53,1661.28 v1(7787.94,1661.28) ; v1@7784.66,1664.36 7819.94,1629.07 7844.9,1629.07 7859.04,1614.93 7890.33,1614.93 7900.58,1604.68 7900.58,1589.58 7906.44,1583.72 7930.45,1583.72 C62_A3.2@7930.57,1583.6
  Bottom Layer w12: C74_A3.2@7755.22,1696.26 7755.22,1746.1 C95_A3.1@7756.34,1747.22 7759.15,1750.03 7759.15,1796.31 R196_A3.2@7761.95,1799.11 7761.95,1845.29 7778.25,1861.59 7866.52,1861.59 7886.4,1881.46 7995.28,1881.46 8022.03,1908.21 8178.89,1908.21 8231.4,1960.71 8316.08,1960.71 8331.43,1976.06 8331.43,2277.15 8324.4,2284.18 8222.71,2284.18 8214.69,2292.2 R71_A3.2@8214.69,2344.23
  other v1: 8277.85,2332.26 8277.85,2365.45 8277.85,2398.63 8277.85,2431.82 8277.85,2465 8277.85,2498.19 8277.85,2531.37
CB13_A4: C62_A4.2 C74_A4.2 C95_A4.1 R71_A4.2 R74_A4.2 R78_A4.2 R82_A4.2 R196_A4.2 U1_A4.12 | length 1609.9
  Top Layer w10: U1_A4.12@10092.41,1531.37 10092.41,1617.78 10106.69,1632.06 10106.69,1651.98 v1(10108.25,1653.54)
  Bottom Layer w10: C74_A4.2@10078.27,1690.24 10092.95,1675.56 10092.95,1672.88 10099.35,1666.48 10099.35,1665.69 10108.25,1656.79 v1(10108.25,1653.54) ; v1@10110.37,1655.66 10140.17,1625.87 10165.13,1625.87 10179.27,1611.72 10210.56,1611.72 10220.81,1601.47 10220.81,1586.37 10226.67,1580.51 10250.68,1580.51 C62_A4.2@10250.8,1580.39
  Bottom Layer w12: C74_A4.2@10075.45,1693.06 10075.45,1742.89 C95_A4.1@10076.57,1744.01 10079.38,1746.82 10079.38,1793.1 R196_A4.2@10082.18,1795.9 10082.18,1842.08 10098.48,1858.38 10186.75,1858.38 10206.63,1878.25 10315.51,1878.25 10342.26,1905 10499.12,1905 10551.63,1957.5 10636.31,1957.5 10651.66,1972.85 10651.66,2273.94 10644.63,2280.97 10542.94,2280.97 10534.92,2288.99 R71_A4.2@10534.92,2341.02
  other v1: 10598.08,2329.05 10598.08,2362.24 10598.08,2395.42 10598.08,2428.61 10598.08,2461.79 10598.08,2494.98 10598.08,2528.16
CB14_A1: C54_A1.2 C74_A1.1 R57_A1.2 R60_A1.2 R64_A1.2 R68_A1.2 R196_A1.1 R202_A1.2 U1_A1.10 | length 1711.4
  Top Layer w10: U1_A1.10@3179.94,1531.37 3179.94,1601.73 3202.71,1624.49 3202.71,1647.45 v1(3205,1649.74)
  Bottom Layer w10: C74_A1.1@3169.73,1690.24 3205,1654.97 v1(3205,1649.74)
  Bottom Layer w12: C74_A1.1@3169.73,1690.24 3173.67,1690.24 3185.6,1702.18 C54_A1.2@3185.6,1744.01 3181.59,1748.03 3181.59,1791.89 R196_A1.1@3180.64,1792.84 ; R196_A1.1@3179.13,1791.34 R196_A1.1@3180.64,1792.84 ; R60_A1.2@3583.08,2656.12 3659.36,2656.12 3670.01,2645.47 3670.01,2597.4 3704.03,2563.38 3704.03,2363.86 3723.9,2343.99 3723.9,1968.84 3692.7,1937.63 3608.02,1937.63 3555.51,1885.13 3398.65,1885.13 3371.9,1858.38 3263.02,1858.38 3243.14,1838.5 3217.1,1838.5 3187.33,1808.73 3187.33,1799.53 R196_A1.1@3180.64,1792.84
  other v1: 3646.24,2634.17 3646.24,2667.36 3646.24,2700.54 3646.24,2733.73 3646.24,2766.91 3646.24,2800.1 3646.24,2833.28
CB14_A2: C54_A2.2 C74_A2.1 R57_A2.2 R60_A2.2 R64_A2.2 R68_A2.2 R196_A2.1 R202_A2.2 U1_A2.10 | length 1711.4
  Top Layer w10: U1_A2.10@5474.96,1531.37 5474.96,1601.73 5497.72,1624.49 5497.72,1647.45 v1(5500.02,1649.74)
  Bottom Layer w10: C74_A2.1@5464.75,1690.24 5500.02,1654.97 v1(5500.02,1649.74)
  Bottom Layer w12: C74_A2.1@5464.75,1690.24 5468.68,1690.24 5480.62,1702.18 C54_A2.2@5480.62,1744.01 5476.61,1748.03 5476.61,1791.89 R196_A2.1@5475.65,1792.84 ; R196_A2.1@5474.15,1791.34 R196_A2.1@5475.65,1792.84 ; R60_A2.2@5878.1,2656.12 5954.37,2656.12 5965.02,2645.47 5965.02,2597.4 5999.05,2563.38 5999.05,2363.86 6018.92,2343.99 6018.92,1968.84 5987.71,1937.63 5903.03,1937.63 5850.53,1885.13 5693.66,1885.13 5666.91,1858.38 5558.03,1858.38 5538.16,1838.5 5512.12,1838.5 5482.34,1808.73 5482.34,1799.53 R196_A2.1@5475.65,1792.84
  other v1: 5941.25,2634.17 5941.25,2667.36 5941.25,2700.54 5941.25,2733.73 5941.25,2766.91 5941.25,2800.1 5941.25,2833.28
CB14_A3: C54_A3.2 C74_A3.1 R57_A3.2 R60_A3.2 R64_A3.2 R68_A3.2 R196_A3.1 R202_A3.2 U1_A3.10 | length 1711.4
  Top Layer w10: U1_A3.10@7811.55,1534.57 7811.55,1604.94 7834.32,1627.7 7834.32,1650.65 v1(7836.62,1652.95)
  Bottom Layer w10: C74_A3.1@7801.34,1693.45 7836.62,1658.18 v1(7836.62,1652.95)
  Bottom Layer w12: C74_A3.1@7801.34,1693.45 7805.28,1693.45 7817.22,1705.38 C54_A3.2@7817.22,1747.22 7813.2,1751.24 7813.2,1795.1 R196_A3.1@7812.25,1796.05 ; R196_A3.1@7810.75,1794.55 R196_A3.1@7812.25,1796.05 ; R60_A3.2@8214.69,2659.32 8290.97,2659.32 8301.62,2648.67 8301.62,2600.61 8335.64,2566.59 8335.64,2367.07 8355.52,2347.2 8355.52,1972.05 8324.31,1940.84 8239.63,1940.84 8187.12,1888.34 8030.26,1888.34 8003.51,1861.59 7894.63,1861.59 7874.76,1841.71 7848.71,1841.71 7818.94,1811.94 7818.94,1802.74 R196_A3.1@7812.25,1796.05
  other v1: 8277.85,2637.38 8277.85,2670.57 8277.85,2703.75 8277.85,2736.93 8277.85,2770.12 8277.85,2803.3 8277.85,2836.49
CB14_A4: C54_A4.2 C74_A4.1 R57_A4.2 R60_A4.2 R64_A4.2 R68_A4.2 R196_A4.1 R202_A4.2 U1_A4.10 | length 1711.4
  Top Layer w10: U1_A4.10@10131.78,1531.37 10131.78,1601.73 10154.55,1624.49 10154.55,1647.45 v1(10156.85,1649.74)
  Bottom Layer w10: C74_A4.1@10121.57,1690.24 10156.85,1654.97 v1(10156.85,1649.74)
  Bottom Layer w12: C74_A4.1@10121.57,1690.24 10125.51,1690.24 10137.45,1702.18 C54_A4.2@10137.45,1744.01 10133.43,1748.03 10133.43,1791.89 R196_A4.1@10132.48,1792.84 ; R196_A4.1@10130.98,1791.34 R196_A4.1@10132.48,1792.84 ; R60_A4.2@10534.92,2656.12 10611.2,2656.12 10621.85,2645.47 10621.85,2597.4 10655.87,2563.38 10655.87,2363.86 10675.75,2343.99 10675.75,1968.84 10644.54,1937.63 10559.86,1937.63 10507.35,1885.13 10350.49,1885.13 10323.74,1858.38 10214.86,1858.38 10194.99,1838.5 10168.94,1838.5 10139.17,1808.73 10139.17,1799.53 R196_A4.1@10132.48,1792.84
  other v1: 10598.08,2634.17 10598.08,2667.36 10598.08,2700.54 10598.08,2733.73 10598.08,2766.91 10598.08,2800.1 10598.08,2833.28
CB15_A1: C36_A1.2 C54_A1.1 R44_A1.2 R47_A1.2 R50_A1.2 R54_A1.2 R197_A1.2 R202_A1.1 U1_A1.8 | length 1995.1
  Top Layer w10: U1_A1.8@3219.31,1531.37 3220.03,1532.09 3220.03,1586.31 3230.55,1596.83 3230.55,1597.77 3237.08,1604.29 3237.08,1607.02 3250.86,1620.8 3250.86,1643.92 v1(3253.16,1646.22)
  Bottom Layer w10: C36_A1.2@3236.57,1690.24 3236.57,1666.06 3253.16,1649.47 v1(3253.16,1646.22)
  Bottom Layer w12: C36_A1.2@3236.57,1690.24 3234.71,1692.1 3234.71,1742.15 C54_A1.1@3232.85,1744.01 3235.03,1746.2 3235.03,1792.75 R197_A1.2@3237.22,1794.94 3241.16,1794.94 3253.28,1807.06 3253.28,1811.88 3279.91,1838.5 3380.13,1838.5 3406.88,1865.25 3649.31,1865.25 3747.44,1963.38 3747.44,2348.56 3723.9,2372.09 3723.9,2768.97 3692.84,2800.04 3692.84,2944.35 3665.98,2971.21 R54_A1.2@3583.08,2971.21
  other v1: 3646.24,2949.13 3646.24,2982.32 3646.24,3015.5 3646.24,3048.69 3646.24,3081.87 3646.24,3115.06 3646.24,3148.24
CB15_A2: C36_A2.2 C54_A2.1 R44_A2.2 R47_A2.2 R50_A2.2 R54_A2.2 R197_A2.2 R202_A2.1 U1_A2.8 | length 1995.1
  Top Layer w10: U1_A2.8@5514.33,1531.37 5515.05,1532.09 5515.05,1586.31 5525.57,1596.83 5525.57,1597.77 5532.1,1604.29 5532.1,1607.02 5545.87,1620.8 5545.87,1643.92 v1(5548.17,1646.22)
  Bottom Layer w10: C36_A2.2@5531.59,1690.24 5531.59,1666.06 5548.17,1649.47 v1(5548.17,1646.22)
  Bottom Layer w12: C36_A2.2@5531.59,1690.24 5529.72,1692.1 5529.72,1742.15 C54_A2.1@5527.86,1744.01 5530.05,1746.2 5530.05,1792.75 R197_A2.2@5532.24,1794.94 5536.17,1794.94 5548.3,1807.06 5548.3,1811.88 5574.92,1838.5 5675.14,1838.5 5701.89,1865.25 5944.33,1865.25 6042.45,1963.38 6042.45,2348.56 6018.92,2372.09 6018.92,2768.97 5987.85,2800.04 5987.85,2944.35 5960.99,2971.21 R54_A2.2@5878.1,2971.21
  other v1: 5941.25,2949.13 5941.25,2982.32 5941.25,3015.5 5941.25,3048.69 5941.25,3081.87 5941.25,3115.06 5941.25,3148.24
CB15_A3: C36_A3.2 C54_A3.1 R44_A3.2 R47_A3.2 R50_A3.2 R54_A3.2 R197_A3.2 R202_A3.1 U1_A3.8 | length 1995.1
  Top Layer w10: U1_A3.8@7850.92,1534.57 7851.65,1535.3 7851.65,1589.52 7862.17,1600.04 7862.17,1600.97 7868.69,1607.5 7868.69,1610.23 7882.47,1624.01 7882.47,1647.13 v1(7884.77,1649.43)
  Bottom Layer w10: C36_A3.2@7868.18,1693.45 7868.18,1669.27 7884.77,1652.68 v1(7884.77,1649.43)
  Bottom Layer w12: C36_A3.2@7868.18,1693.45 7866.32,1695.31 7866.32,1745.36 C54_A3.1@7864.46,1747.22 7866.65,1749.41 7866.65,1795.96 R197_A3.2@7868.83,1798.14 7872.77,1798.14 7884.9,1810.27 7884.9,1815.09 7911.52,1841.71 8011.74,1841.71 8038.49,1868.46 8280.93,1868.46 8379.05,1966.58 8379.05,2351.77 8355.52,2375.3 8355.52,2772.18 8324.45,2803.25 8324.45,2947.56 8297.59,2974.42 R54_A3.2@8214.69,2974.42
  other v1: 8277.85,2952.34 8277.85,2985.53 8277.85,3018.71 8277.85,3051.9 8277.85,3085.08 8277.85,3118.27 8277.85,3151.45
CB15_A4: C36_A4.2 C54_A4.1 R44_A4.2 R47_A4.2 R50_A4.2 R54_A4.2 R197_A4.2 R202_A4.1 U1_A4.8 | length 1995.1
  Top Layer w10: U1_A4.8@10171.15,1531.37 10171.88,1532.09 10171.88,1586.31 10182.4,1596.83 10182.4,1597.77 10188.92,1604.29 10188.92,1607.02 10202.7,1620.8 10202.7,1643.92 v1(10205,1646.22)
  Bottom Layer w10: C36_A4.2@10188.41,1690.24 10188.41,1666.06 10205,1649.47 v1(10205,1646.22)
  Bottom Layer w12: C36_A4.2@10188.41,1690.24 10186.55,1692.1 10186.55,1742.15 C54_A4.1@10184.69,1744.01 10186.88,1746.2 10186.88,1792.75 R197_A4.2@10189.06,1794.94 10193,1794.94 10205.13,1807.06 10205.13,1811.88 10231.75,1838.5 10331.97,1838.5 10358.72,1865.25 10601.16,1865.25 10699.28,1963.38 10699.28,2348.56 10675.75,2372.09 10675.75,2768.98 10644.68,2800.04 10644.68,2944.35 10617.82,2971.21 R54_A4.2@10534.92,2971.21
  other v1: 10598.08,2949.13 10598.08,2982.32 10598.08,3015.5 10598.08,3048.69 10598.08,3081.87 10598.08,3115.06 10598.08,3148.24
CB16_A1: C17_A1.2 C36_A1.1 R29_A1.2 R32_A1.2 R35_A1.2 R40_A1.2 R197_A1.1 R203_A1.2 U1_A1.6 | length 1077.2
  Top Layer w10: U1_A1.6@3258.68,1531.37 3259.5,1532.19 3259.5,1575.89 3265.21,1581.6 3265.21,1584.69 3270.83,1590.31 3270.83,1593.04 3296.61,1618.83 3296.61,1633.3 v1(3298.91,1635.6)
  Bottom Layer w10: C36_A1.1@3283.81,1690.24 3283.81,1650.7 v1(3298.91,1635.6)
  Bottom Layer w12: C36_A1.1@3283.81,1690.24 3285.3,1690.24 3291.11,1696.05 C17_A1.2@3291.11,1744.01 3287.79,1747.33 3287.79,1791.61 R197_A1.1@3284.46,1794.94 3288.4,1794.94 3311.15,1817.68 3311.15,1818.63 3388.36,1818.63 3415.11,1845.38 3657.55,1845.38 3764.79,1952.62 3813.96,1952.62 3815.95,1950.63 3847.72,1950.63 3882.48,1985.4 3885.28,1985.4 3885.28,2013.69 3899.45,2027.86 R35_A1.2@3899.45,2081.65
  other v1: 3893.76,2154.49 3923.29,2154.49 3893.76,2187.68 3923.29,2187.68 3893.76,2220.86 3923.29,2220.86
CB16_A2: C17_A2.2 C36_A2.1 R29_A2.2 R32_A2.2 R35_A2.2 R40_A2.2 R197_A2.1 R203_A2.2 U1_A2.6 | length 1077.2
  Top Layer w10: U1_A2.6@5553.7,1531.37 5554.52,1532.19 5554.52,1575.89 5560.22,1581.6 5560.22,1584.69 5565.85,1590.31 5565.85,1593.04 5591.63,1618.83 5591.63,1633.3 v1(5593.93,1635.6)
  Bottom Layer w10: C36_A2.1@5578.83,1690.24 5578.83,1650.7 v1(5593.93,1635.6)
  Bottom Layer w12: C36_A2.1@5578.83,1690.24 5580.31,1690.24 5586.12,1696.05 C17_A2.2@5586.12,1744.01 5582.8,1747.33 5582.8,1791.61 R197_A2.1@5579.48,1794.94 5583.42,1794.94 5606.17,1817.68 5606.17,1818.63 5683.38,1818.63 5710.13,1845.38 5952.56,1845.38 6059.81,1952.62 6108.98,1952.62 6110.97,1950.63 6142.74,1950.63 6177.5,1985.4 6180.3,1985.4 6180.3,2013.69 6194.47,2027.86 R35_A2.2@6194.47,2081.65
  other v1: 6188.77,2154.49 6218.3,2154.49 6188.77,2187.68 6218.3,2187.68 6188.77,2220.86 6218.3,2220.86
CB16_A3: C17_A3.2 C36_A3.1 R29_A3.2 R32_A3.2 R35_A3.2 R40_A3.2 R197_A3.1 R203_A3.2 U1_A3.6 | length 1077.2
  Top Layer w10: U1_A3.6@7890.29,1534.57 7891.11,1535.39 7891.11,1579.1 7896.82,1584.81 7896.82,1587.9 7902.44,1593.52 7902.44,1596.25 7928.23,1622.03 7928.23,1636.51 v1(7930.53,1638.81)
  Bottom Layer w10: C36_A3.1@7915.43,1693.45 7915.43,1653.91 v1(7930.53,1638.81)
  Bottom Layer w12: C36_A3.1@7915.43,1693.45 7916.91,1693.45 7922.72,1699.26 C17_A3.2@7922.72,1747.21 7919.4,1750.54 7919.4,1794.82 R197_A3.1@7916.08,1798.14 7920.01,1798.14 7942.76,1820.89 7942.76,1821.84 8019.97,1821.84 8046.72,1848.59 8289.16,1848.59 8396.4,1955.83 8445.57,1955.83 8447.57,1953.84 8479.33,1953.84 8514.1,1988.6 8516.9,1988.6 8516.9,2016.9 8531.06,2031.07 R35_A3.2@8531.06,2084.86
  other v1: 8525.37,2157.7 8554.9,2157.7 8525.37,2190.89 8554.9,2190.89 8525.37,2224.07 8554.9,2224.07
CB16_A4: C17_A4.2 C36_A4.1 R29_A4.2 R32_A4.2 R35_A4.2 R40_A4.2 R197_A4.1 R203_A4.2 U1_A4.6 | length 1077.2
  Top Layer w10: U1_A4.6@10210.52,1531.37 10211.34,1532.19 10211.34,1575.89 10217.05,1581.6 10217.05,1584.69 10222.67,1590.31 10222.67,1593.04 10248.46,1618.83 10248.46,1633.3 v1(10250.76,1635.6)
  Bottom Layer w10: C36_A4.1@10235.66,1690.24 10235.66,1650.7 v1(10250.76,1635.6)
  Bottom Layer w12: C36_A4.1@10235.66,1690.24 10237.14,1690.24 10242.95,1696.05 C17_A4.2@10242.95,1744.01 10239.63,1747.33 10239.63,1791.61 R197_A4.1@10236.31,1794.94 10240.24,1794.94 10262.99,1817.68 10262.99,1818.63 10340.2,1818.63 10366.95,1845.38 10609.39,1845.38 10716.63,1952.62 10765.8,1952.62 10767.8,1950.63 10799.56,1950.63 10834.33,1985.4 10837.13,1985.4 10837.13,2013.69 10851.29,2027.86 R35_A4.2@10851.29,2081.65
  other v1: 10845.6,2154.49 10875.13,2154.49 10845.6,2187.68 10875.13,2187.68 10845.6,2220.86 10875.13,2220.86
CB17_A1: C4_A1.2 C17_A1.1 R15_A1.2 R18_A1.2 R22_A1.2 R25_A1.2 R198_A1.2 R203_A1.1 U1_A1.4 | length 1594.2
  Top Layer w10: U1_A1.4@3298.05,1531.37 3298.96,1532.27 3298.96,1570.71 3304.58,1576.34 3304.58,1579.06 3333.03,1607.51 3335.76,1607.51 v1(3363.84,1635.6)
  Bottom Layer w10: C4_A1.2@3343.38,1690.14 3343.38,1656.07 v1(3363.84,1635.6)
  Bottom Layer w12: C4_A1.2@3343.38,1690.14 3340.86,1692.66 3340.86,1741.49 C17_A1.1@3338.35,1744.01 3338.35,1785.65 3351.46,1798.76 3396.59,1798.76 3423.34,1825.5 3665.78,1825.5 3745.65,1905.38 R203_A1.1@3815.95,1905.38 3817.64,1907.06 3865.6,1907.06 R198_A1.2@3867.28,1908.75 3867.28,1905 3900.53,1905 3969.17,1973.65 3969.17,2100.78 3976.37,2107.97 3976.37,2386.52 3969.34,2393.55 3906.48,2393.55 3899.45,2400.58 R18_A1.2@3899.45,2488.51
  other v1: 3893.76,2558.04 3923.29,2558.04 3893.76,2591.22 3923.29,2591.22 3893.76,2624.41 3923.29,2624.41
